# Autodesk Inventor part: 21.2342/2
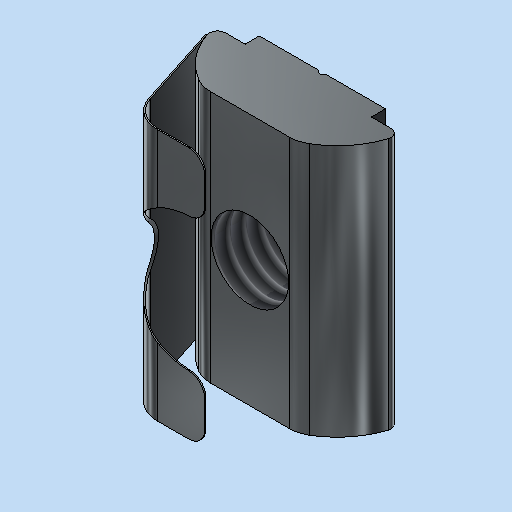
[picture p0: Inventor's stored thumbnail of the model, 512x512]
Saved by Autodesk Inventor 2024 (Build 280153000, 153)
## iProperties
Created: 2012-02
Part Number: 21.2342/2
Document SubType Name: Modeling
Designer: Administrator
Density: 7.85 g/cm^3
Material: Steel
Mass: 4.86141 g
Surface Area: 8.61152 cm^2
Volume: 0.619288 cm^3
Description: M6 SQUARE NUT 30 W/ POS. FXG.
Vendor: S
Appearance: Zinc
Author: Administrator
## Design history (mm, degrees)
sketch "Sketch1"
  geometry: L1 (-4, 0)-(4, 0); L2 (4, 0)-(4, -0.9); L3 (-4, 0)-(-4, -0.9); L4 (-4, -0.9)-(-5.25, -0.9); L5 (4, -0.9)-(5.25, -0.9); L6 (-2.5, -4.6)-(2.5, -4.6); A1 r 5 centre (-0.966, -0.022) between (-5.726, -1.553) and (-3.522, -4.319); A2 r 5 centre (0.966, -0.022) between (3.522, -4.319) and (5.726, -1.553); A3 r 0.5 centre (5.25, -1.4) between (5.726, -1.553) and (5.25, -0.9); A4 r 0.5 centre (-5.25, -1.4) between (-5.25, -0.9) and (-5.726, -1.553); A5 r 2 centre (-2.5, -2.6) between (-3.522, -4.319) and (-2.5, -4.6); A6 r 2 centre (2.5, -2.6) between (2.5, -4.6) and (3.522, -4.319); 3 further points
  constraints: 12 end point, 12 point on circle, 8 tangent, 6 centre point, 2 equal length, 2 equal radius, 2 midpoint, 2 parallel, 2 perpendicular, 1 coincident, 1 collinear, 1 horizontal, 1 vertical alignment
  dimensions: "d0" = 0.9 distance of L1.end L2.end; "d1" = 8 distance of L1.start L1.end; "d2" = 4.6 distance between parallel lines of L6 L1; "d4" = 5 radius of A1; "d5" = 5 radius of A2 (= d4); "d6" = 0.5 radius of A3; "d7" = 2 radius of A5; "d8" = 11.5 dimension on A3 A4; "d9" = 5 distance of L6.start L6.end
extrude "Extrusion1" new body sketch "Sketch1" stored distance "d10" = 16; taper "d11" = 0 deg
sketch "Sketch2"
  geometry: L1 (-4, 0)-(4, 0) reference; L2 (-0.25, 0)-(0, -0.25); L3 (0, -0.25)-(0.25, 0); 2 further points
  constraints: 4 end point, 2 point on line, 1 midpoint, 1 vertical alignment
  dimensions: "d12" = 45 deg angle of L1 L2; "d13" = 90 deg angle of L3 L2; "d14" = 0.25 distance from line of L2.end L1
extrude "Extrusion2" cut sketch "Sketch2" extent not by distance; stored distance "d15" = 16; taper "d16" = 0 deg
fillet "Fillet1" dims "d17" = 0.2
sketch "Sketch3"
  geometry: 2 further points
  constraints: 1 coincident
hole "Hole1" sketch "Sketch3" diameter "d18" = 4.917; stored, may be unused: countersink angle "d22" = 90 deg, drill point angle "d24" = 118 deg; dims "d19" = 6, "d20" = 4, "d21" = 2, "d23" = 8
sketch "Sketch4"
  geometry: L1 (-5.726, -1.553)-(-4.005, -6.901); L2 (-2.102, -8.288)-(0.898, -8.288); L3 (-4, 0)-(-0.25, 0) reference; L4 (0.898, -8.368)-(-2.102, -8.368); L5 (-4.082, -6.925)-(-5.802, -1.578); L6 (-5.802, -1.578)-(-5.726, -1.553); L7 (0.898, -8.288)-(0.898, -8.368); L8 (-4, -0.9)-(-5.25, -0.9) reference; A1 r 2 centre (-2.102, -6.288) between (-4.005, -6.901) and (-2.102, -8.288); A2 r 2.08 centre (-2.102, -6.288) between (-4.082, -6.925) and (-2.102, -8.368); A3 r 5 centre (-0.966, -0.022) between (-5.726, -1.553) and (-3.522, -4.319) reference; 1 further point
  constraints: 12 end point, 4 point on circle, 3 tangent, 2 centre point, 2 perpendicular, 1 horizontal, 2 other
  dimensions: "d26" = 2 radius of A1; "d27" = 0.08 distance between parallel lines of L5 L1; "d28" = 3 distance of L4.start L4.end; "d35" = 7.468 distance between parallel lines of L4 L8
extrude "Extrusion3" join sketch "Sketch4" stored distance "d29" = 16; taper "d30" = 0 deg
sketch "Sketch5"
  geometry: L1 (5, 0)-(5, -16) reference; L2 (2.5, -12.25)-(15.825, -12.25); L3 (15.825, -12.25)-(15.825, -3.75); L4 (15.825, -3.75)-(2.5, -3.75); C1 r 2.458 at (2.5, -8) reference; A1 r 4.25 centre (2.5, -8) between (2.5, -3.75) and (2.5, -12.25)
  constraints: 6 end point, 2 point on circle, 2 tangent, 1 centre point, 1 coincident, 1 perpendicular, 1 vertical, 1 vertical alignment
  dimensions: "d31" = 8.5 diameter of A1
extrude "Extrusion4" cut sketch "Sketch5" distance "d32" = 16; taper "d33" = 0 deg
fillet "Fillet2" dims "d34" = 1
body "Solid1"
